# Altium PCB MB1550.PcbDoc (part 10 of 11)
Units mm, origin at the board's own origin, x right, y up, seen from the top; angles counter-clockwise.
Board outline 154.81 x 170.69 mm, 6 copper layers (Top Layer, Signal Layer 1, Signal Layer 2, Signal Layer 3, Signal Layer 4, Bottom Layer), stack 1.49 mm thick; 810 components, 633 nets, 2973 pads, 2150 vias.
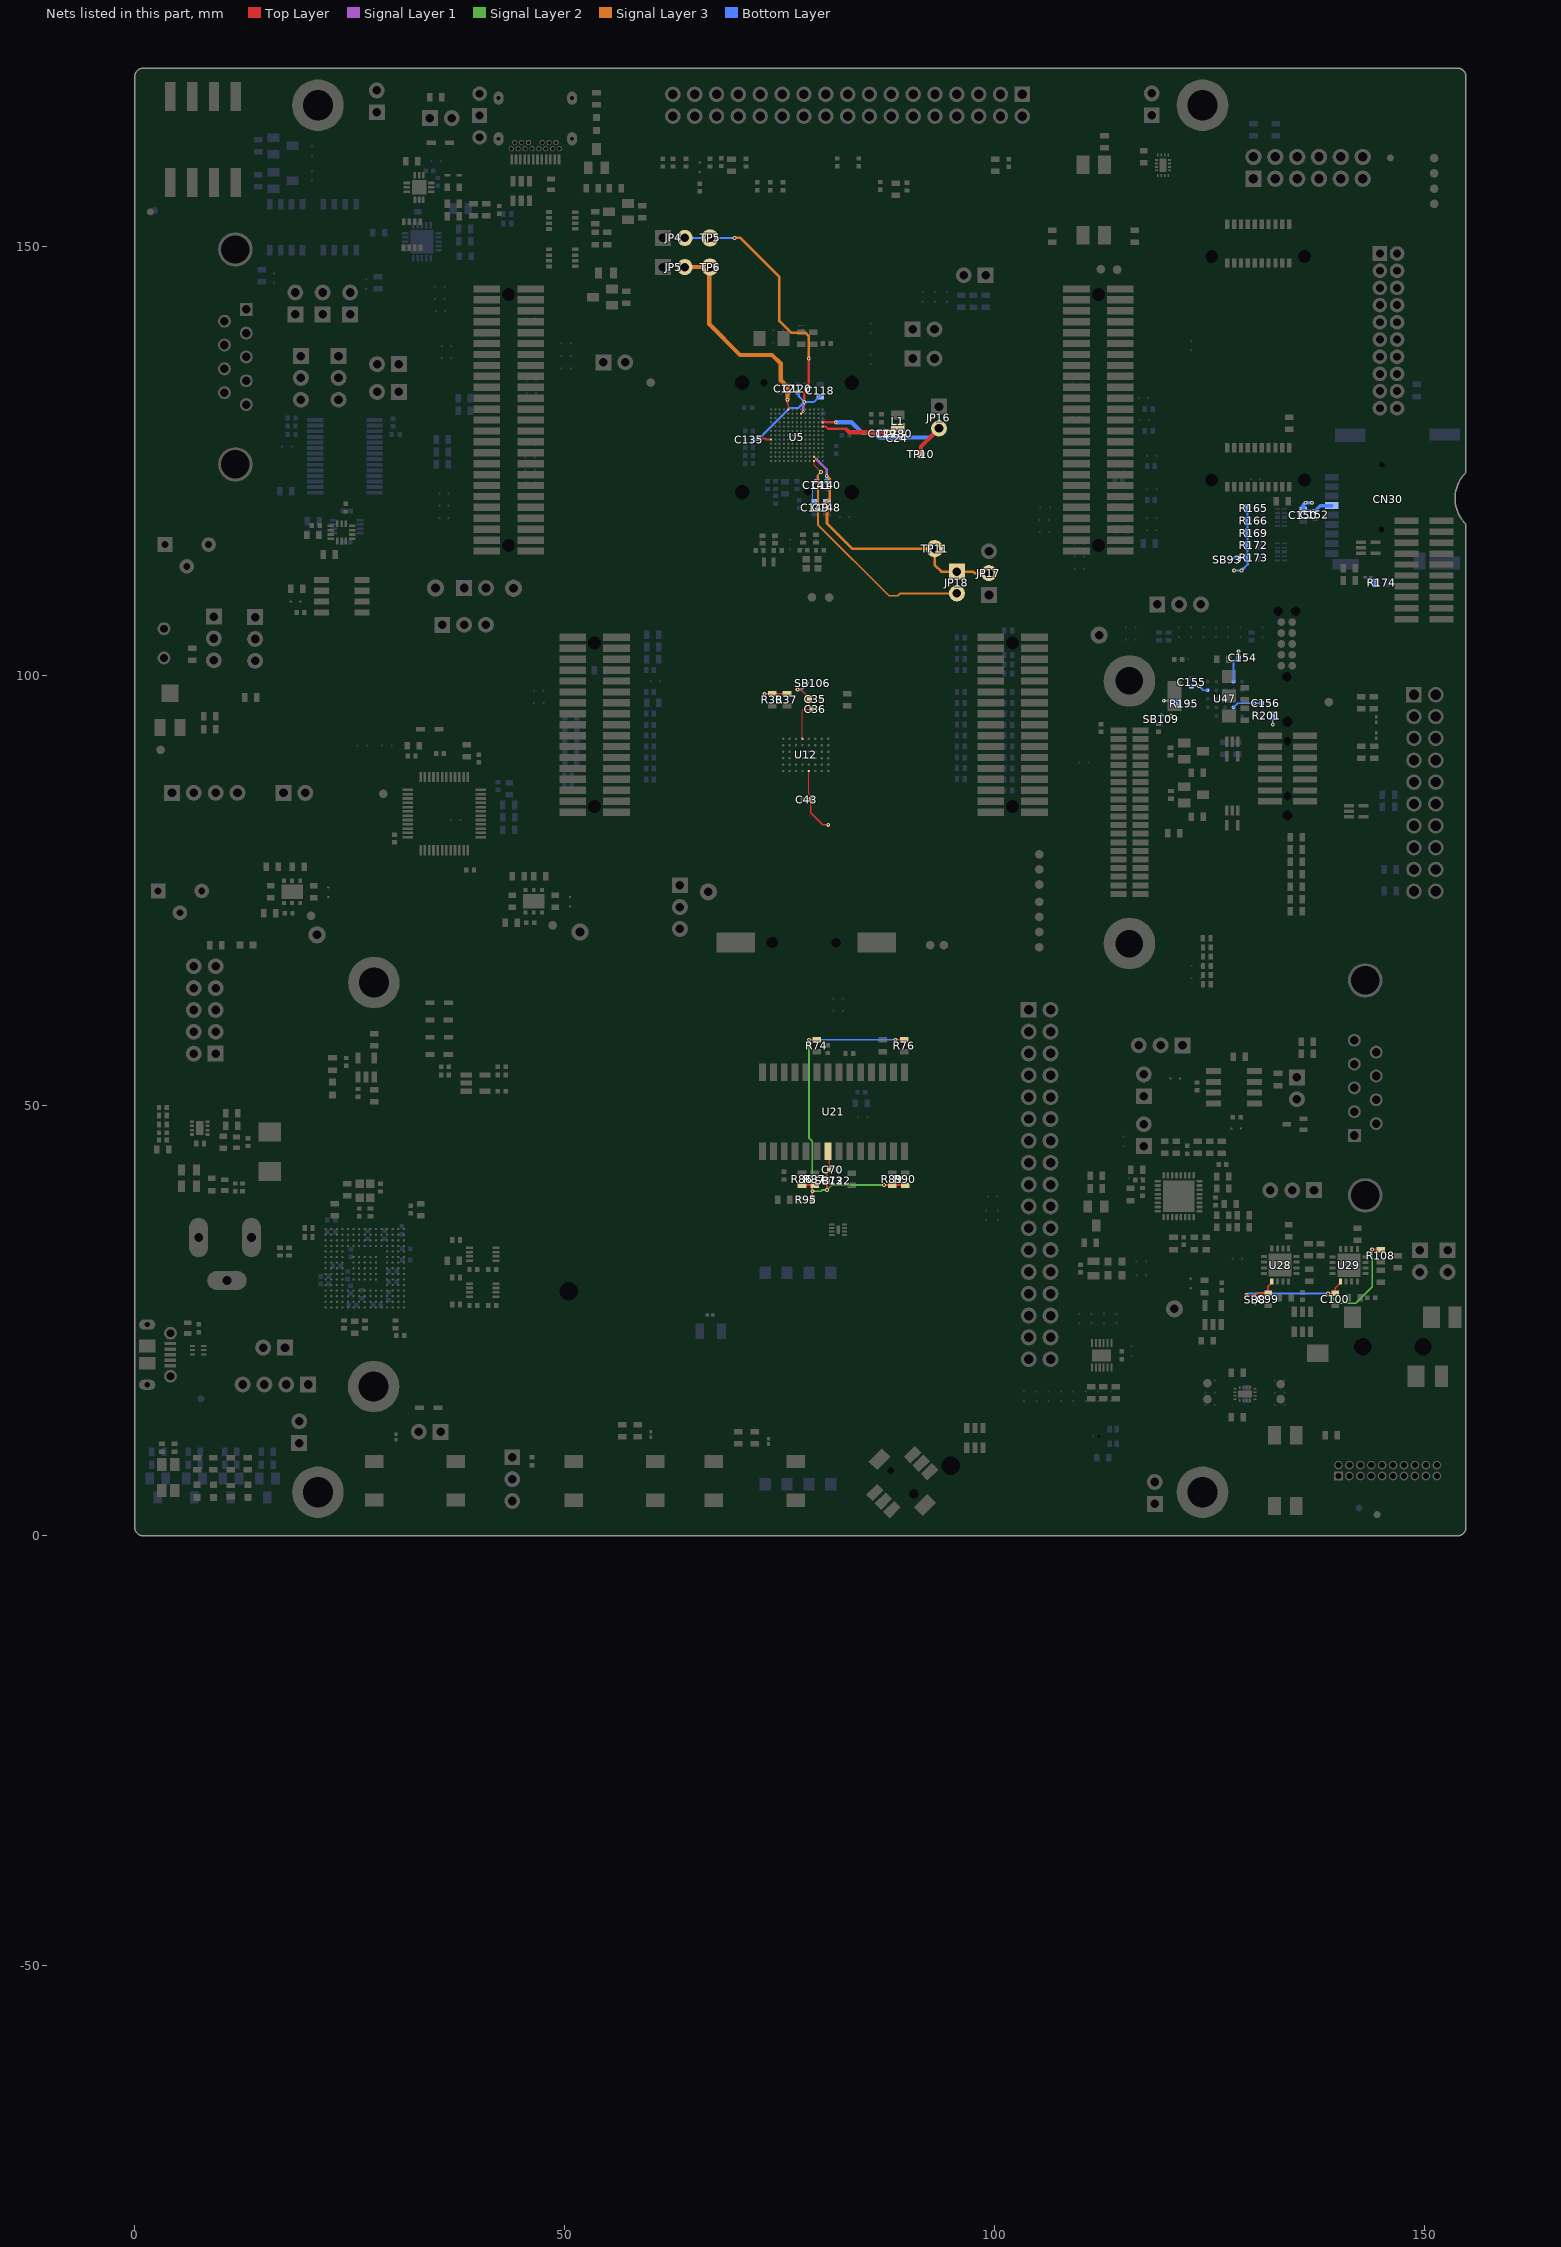
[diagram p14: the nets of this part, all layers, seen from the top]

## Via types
v1: diameter 0.45, hole 0.2, Top Layer to Bottom Layer, tented both sides, 1777 vias
v2: diameter 0.25, hole 0.1, Top Layer to Signal Layer 1, tented top, 344 vias
v3: diameter 0.25, hole 0.1, Signal Layer 1 to Signal Layer 2, 29 vias

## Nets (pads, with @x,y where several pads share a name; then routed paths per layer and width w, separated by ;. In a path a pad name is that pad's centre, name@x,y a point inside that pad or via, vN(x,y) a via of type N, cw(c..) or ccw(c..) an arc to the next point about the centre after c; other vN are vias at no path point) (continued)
VDD_OCTOSPI_2_FLASH: C154.2 C155.2 C156.2 R195.2 R201.1 SB109.2 U47.B4 U47.D1 U47.E4 | length 13.5
  Bottom Layer w0.2: SB109.2@119.384,95.521 119.529,95.375 v1(120.5,95.375) ; v1(119.675,97.125) 121.225,97.125 121.334,97.016 R195.2@121.334,96.771 ; C155.2@122.9,98.825 v1(123.775,98.825) 124.254,98.346 U47.D1@124.784,98.346 ; U47.B4@127.784,96.346 128.262,96.824 v1(130.225,96.825) C156.2@131.05,96.825 ; U47.E4@127.784,99.346 127.784,101.534 C154.2@128.375,102.125 v1(128.375,102.875) ; v1(132.334,94.359) R201.1@132.334,95.371
VDD_SC: C70.1 C73.2 R74.2 R76.2 R86.2 R87.2 R89.2 R90.2 R95.2 SB122.2 U21.21 | length 50.4
  Top Layer w0.2: R86.2@77.6,40.8 R87.2@78.75,40.8 ; v1(78.4,57.7) R74.2@79.3,57.7 ; R95.2@78.8,39.1 78.8,40.7 R87.2@78.725,40.775 ; v1(80.5,40.225) C73.2@80.5,41.3 80.5,42.3 80.75,42.55 C70.1@80.75,42.6 80.75,44.616 U21.21@80.615,44.751 ; v1(87.141,40.807) 87.148,40.8 R89.2@88.1,40.8 R90.2@89.6,40.8 ; v1(88.45,57.7) R76.2@89.5,57.7 ; R87.2@78.725,40.775 R87.2@78.75,40.8 ; R87.2@78.725,40.775 79.075,40.775 R87.2@79.1,40.8 R87.2@78.75,40.8
  Signal Layer 2 w0.2: v1(78.4,57.7) 78.4,46.302 78.8,45.902 v1(78.8,40.075) 79.766,40.075 79.916,40.225 v1(80.5,40.225) 81.083,40.807 v1(87.141,40.807)
  Bottom Layer w0.2: v1(78.4,57.7) v1(88.45,57.7) ; v1(80.5,40.225) 80.5,41.1 SB122.2@80.7,41.3
VDD_SDCARD: C150.1 C152.2 CN30.4 R165.2 R166.2 R169.2 R172.2 R173.2 R174.2 SB93.2 | length 16.4
  Bottom Layer w0.25: SB93.2@127.575,113.525 127.8,113.75 R173.2@129.425,113.75 129.425,112.988 v1(128.699,112.263) 128.687,112.275 v1(127.85,112.275) ; R173.2@129.425,113.75 R172.2@129.425,115.175 R169.2@129.425,116.625 R166.2@129.425,118.05 R165.2@129.425,119.5 ; v1(143.525,110.85) R174.2@144.325,110.85
  Bottom Layer w0.4: v1(136.9,120.15) v1(136.15,120.15) 135.9,119.9 C150.1@135.9,119.4 136.125,119.175 C152.2@137.25,119.175 137.887,119.812 CN30.4@139.198,119.812
VDD_SRAM: C35.2 C36.2 C43.2 R36.1 R37.2 SB106.2 U12.D6 U12.E1 | length 19.2
  Top Layer w0.1: U12.D6@77.65,92.696 77.65,95.975 77.825,96.15 C36.2@78.7,96.15 78.45,96.4 78.45,96.625 ; U12.E1@78.4,88.946 78.4,86.3 78.6,86.1 C43.2@78.6,85.625 78.6,84.85
  Top Layer w0.2: v1(73.25,97.925) R36.1@74.15,97.925 R37.2@75.85,97.925 ; v1(77.095,98.431) 77.433,98.431 78.45,97.414 C35.2@78.45,97.3 78.45,96.625 ; 78.6,84.85 78.6,84.099 80.012,82.687 v1(80.651,82.687)
  Bottom Layer w0.2: v1@77.095,98.436 77.586,98.436 SB106.2@78.3,99.15
VDD_STPMS2: C99.2 C100.2 R108.2 SB8.2 U28.1 U29.1 | length 27.9
  Top Layer w0.2: v1(129.3,28) SB8.2@130.3,28 130.5,28.2 C99.2@131.8,28.2 131.8,29.025 132.225,29.45 U28.1@132.225,29.6 ; v1(138.775,28.2) C100.2@139.6,28.2 139.6,28.825 140.225,29.45 U29.1@140.225,29.58 ; v1(143.9,33.3) R108.2@144.9,33.3
  Signal Layer 2 w0.2: v1(138.775,28.2) 139.915,27.06 141.972,27.06 143.9,28.987 v1(143.9,33.3)
  Bottom Layer w0.2: v1(129.3,28) 129.5,28.2 v1(138.775,28.2)
VDD_USB: C121.2 JP5.2 TP6.1 U5.E13 | length 26.4
  Top Layer w0.2: v1(75.9,132.125) 75.9,131.73 76,131.629 U5.E13@76,131
  Signal Layer 3 w0.5: JP5.2@63.97,147.55 TP6.1@66.9,147.55 66.805,147.455 66.805,140.919 70.396,137.328 74.119,137.328 75.118,136.329 75.118,134.401 75.9,133.619 v1(75.9,132.125)
  Bottom Layer w0.1: v1(75.9,132.125) 75.9,132.9 C121.2@75.975,132.975
VDDA: C140.2 C148.1 JP17.2 JP18.1 TP11.1 U5.L2 | length 32.2
  Top Layer w0.25: U5.L2@79,125.5 v2(79.25,125.25)
  Signal Layer 1 w0.3: v2(79.25,125.25) 80.475,124.025 v1(80.475,123.25)
  Signal Layer 3 w0.3: v1(80.475,123.25) 80.818,122.907 80.818,120.628 80.5,120.31 v1(80.5,119.675) 80.5,117.732 83.432,114.8 TP11.1@93.025,114.8 93.025,112.922 93.807,112.14 JP18.1@95.609,112.14 97.491,112.14 97.671,111.96 JP17.2@99.34,111.96
  Bottom Layer w0.3: C140.2@80.475,122.65 v1(80.475,123.25) ; v1(80.5,119.675) C148.1@80.5,120.275
VDDIO: C118.2 C120.2 C135.2 JP4.2 TP5.1 U5.A6 U5.H12 | length 44.3
  Top Layer w0.25: v1(72.6,127.6) 73.324,127.6 73.424,127.5 U5.A6@74,127.5 ; U5.H12@77.5,130.5 v2(77.75,130.75) ; v1(77.865,131.872) 77.865,132.945 78.375,133.455 v1(78.375,136.925)
  Signal Layer 1 w0.25: v2(77.75,130.75) 77.75,131.472 77.865,131.586 v1(77.865,131.872)
  Signal Layer 3 w0.3: v1(69.75,150.945) 70.43,150.945 71.375,150 74.975,146.4 74.975,141.275 76.325,139.925 78,139.925 78.375,139.55 v1(78.375,136.925)
  Bottom Layer w0.25: JP4.2@63.97,150.945 TP5.1@66.9,150.945 v1(69.75,150.945) ; C135.2@71.9,127.45 72.45,127.45 v1(72.6,127.6) 76.164,131.164 77.157,131.164 v1(77.865,131.872) ; C120.2@77.1,132.975 77.212,132.864 77.212,132.525 v1(77.865,131.872) ; C118.2@79.725,132.475 79.609,132.475 79.006,131.872 v1(77.865,131.872)
VDDSMPS_CIN: C128.2 C129.2 C130.2 JP16.2 TP10.1 U5.N10 | length 18.5
  Top Layer w0.25: U5.N10@80,129.5 v1(81.525,129.5)
  Top Layer w0.5: TP10.1@91.425,125.8 91.425,126.685 JP16.2@93.525,128.785
  Bottom Layer w0.5: v1(81.525,129.5) 83.365,129.5 84.559,128.306 85.97,128.306 86.538,127.737 C129.2@87.013,127.737 C128.2@87.913,127.737 C130.2@88.763,127.737 92.478,127.737 JP16.2@93.525,128.785
VLX: C24.2 L1.2 U5.N9 | length 10.7
  Top Layer w0.102: L1.2@88.635,128.759 L1.2@88.725,128.85
  Top Layer w0.2: 82.705,128.745 82.783,128.667
  Top Layer w0.25: U5.N9@80,129 80.364,129 80.618,128.745 82.705,128.745
  Top Layer w0.5: 82.783,128.667 83.117,128.333 87.794,128.333 88.073,128.612 88.488,128.612 L1.2@88.725,128.85 89.15,128.425 C24.2@89.15,127.625
VREFP: C141.2 C149.1 JP18.2 U5.L1 | length 31.5
  Top Layer w0.08: U5.L1@79,125 79,124.525 v1(79.8,123.725)
  Signal Layer 3 w0.2: v1(79.8,123.725) 79.446,123.371 79.446,117.599 87.72,109.325 88.75,109.325 89.025,109.6 JP18.2@95.609,109.6
  Bottom Layer w0.1: C149.1@79.125,120.275 78.875,120.525 78.875,122.175 C141.2@79.35,122.65 79.35,123.275 v1(79.8,123.725)
pads on no net: B1.NPTH1 B1.NPTH2 CN1.A2 CN1.A3 CN1.A8 CN1.A10 CN1.A11 CN1.B2 CN1.B3 CN1.B8 CN1.B10 CN1.B11 CN3.9 CN3.10 CN4.1 CN4.3 CN4.7 CN5.5 CN5.6 CN5.7 CN5.8 CN5.9 CN5.10 CN5.11 CN5.12 CN5.NPTH1 CN5.NPTH2 CN6.1 CN6.4 CN6.9 CN9.NPTH1 CN9.NPTH2 CN10.NPTH1 CN10.NPTH2 CN11.NPTH1 CN11.NPTH2 CN12.7 CN13.7 CN13.11 CN13.12 CN13.13 CN14.3 CN14.5 CN14.29 CN14.30 CN14.NPTH1 CN14.NPTH2 CN15.29 CN15.NPTH1 CN15.NPTH2 CN16.5 CN16.6 CN16.9 CN16.10 CN18.0 CN18.1 CN18.2 CN18.9 CN21.NPTH1 CN21.NPTH2 CN22.1 CN22.4 CN22.8 CN23.29 CN26.4 CN27.5 CN27.7 CN27.MT1 CN27.MT2 CN29.8 CN29.9 CN29.10 CN29.11 CN29.13 CN29.14 CN29.15 CN29.16 CN29.17 CN29.18 CN30.NPTH1 CN30.NPTH2 CN31.C6 CN31.NPTH1 CN31.NPTH2 Mire1.1 Mire2.1 Mire3.1 Mire4.1 Mire5.1 Mire6.1 U1.17 U3.5 U5.0 U6.9 U6.10 U6.11 U12.E3 U15.3 U15.4 U15.5 U15.6 U15.25 U15.38 U21.10 U21.25 U25.19 U25.20 U25.23 U25.24 U26.A1 U26.A2 U26.A3 U26.A4 U26.A5 U26.A6 U26.A8 U26.A9 U26.A10 U26.A11 U26.A12 U26.A13 U26.B1 U26.B2 U26.B3 U26.B4 U26.B5 U26.B6 U26.B7 U26.B8 U26.B9 U26.B10 U26.B11 U26.B12 U26.B13 U26.B14 U26.B15 U26.C2 U26.C3 U26.C4 U26.C11 U26.C12 U26.C13 U26.C14 U26.C15 U26.D1 U26.D2 U26.D3 U26.D4 U26.D10 U26.D11 U26.D13 U26.D14 U26.E1 U26.E2 U26.E3 U26.E4 U26.E12 U26.E13 U26.E14 U26.E15 U26.F1 U26.F4 U26.F14 U26.G4 U26.G14 U26.G15 U26.H1 U26.H2 U26.H3 U26.H4 U26.H14 U26.H15 U26.J2 U26.J3 U26.J4 U26.K1 U26.K2 U26.K3 U26.K12 U26.K14 U26.K15 U26.L1 U26.L3 U26.L12 U26.L13 U26.L14 U26.L15 U26.M2 U26.M3 U26.M4 U26.M5 U26.M6 U26.M7 U26.M12 U26.M13 U26.M14 U26.M15 U26.N2 U26.N4 U26.N5 U26.N6 U26.N7 U26.N11 U26.N13 U26.N14 U26.N15 U26.P2 U26.P4 U26.P5 U26.P6 U26.P7 U26.P8 U26.P9 U26.P10 U26.P11 U26.P12 U26.P13 U26.P14 U26.P15 U26.R2 U26.R3 U26.R6 U26.R7 U26.R8 U26.R9 U26.R10 U26.R11 U26.R12 U26.R13 U27.2 U28.16 U29.16 U36.4 U37.7 U37.12 U37.17 U43.8 U43.11 U43.12 U43.15 U43.18 U43.19 U43.21 U46.4 U46.5 U46.6 U46.7 U47.A2 U47.B1 U47.B5 U48.6
copper on no net:
  other v2: 47.8,78.1 19.7,79.2

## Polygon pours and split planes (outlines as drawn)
GND on Top Layer "NO_TH" (solid, pour order 216): -0.141,172.917 154.285,172.917 157.49,169.712 157.49,0.45 154.522,-2.518 0.215,-2.518 -3.055,0.753 -3.055,170.887 -1.026,172.916
5V_EXT on Top Layer "NO_TH" (solid, pour order 214): 7.649,45.232 7.649,46.04 8.094,46.486 8.094,46.829 8.211,46.946 12.585,46.946 14.228,48.59 17.454,48.59 17.925,48.119 17.925,45.824 17.548,45.447 13.993,45.447 13.652,45.788 9.326,45.788 8.63,45.092 7.757,45.092 7.651,45.198
5V_UNPROTECT on Top Layer "NO_TH" (solid, pour order 215): 6.999,46.588 7.523,46.064 7.523,45.182 7.433,45.091 6.837,45.091 6.493,45.436 6.493,46.073 6.107,46.466 4.783,46.466 4.652,46.335 4.652,44.83 6.182,43.299 6.182,41.786 6.183,41.754 6.049,41.62 4.577,41.62 3.28,42.917 3.28,47.135 3.569,47.424 6.92,47.424 6.999,47.345
GND_EXT_UNFILT on Top Layer "NO_TH" (solid, pour order 213): 13.927,28.587 13.927,30.169 11.224,32.872 11.224,36.754 13.32,38.85 13.32,40.187 12.969,40.538 8.55,40.538 7.641,41.447 6.578,41.447 6.335,41.203 6.335,39.03 5.312,38.007 5.312,30.463 7.709,28.065 13.469,28.065 13.928,28.525 13.928,28.569
5V_EXT_UNFILT on Top Layer "NO_TH" (solid, pour order 176): 15.588,33.276 15.588,39.761 12.879,42.471 9.609,42.471 8.541,43.538 6.625,43.538 6.338,43.251 6.338,41.842 6.625,41.554 7.707,41.554 8.678,40.583 12.988,40.583 13.358,40.213 13.358,38.708 11.387,36.738 11.387,32.947 12.851,31.483 14.411,31.483 14.411,31.511 15.602,32.701
UCPD_SOURCE on Top Layer "NO_TH" (solid, pour order 158): 45.368,150.493 44.125,149.25 44.125,147.6 44.95,146.775 47,146.787 49.986,146.787 50.39,147.192 50.39,150.285 50.292,150.391 50.19,150.493
3V3 on Top Layer "NO_TH" (solid, pour order 175): 52.782,68.783 51.119,68.783 49.874,70.027 49.874,73.174 50.003,73.303 51.776,73.303 53.12,71.959 53.12,68.9 53.002,68.782
VBUSc on Top Layer "NO_TH" (solid, pour order 151): 47.65,150.575 49.456,150.575 50.2,151.319 50.2,154.504 49.87,154.834 48.404,154.834 47.49,153.921 47.49,150.677 47.594,150.573
NetC115_1 on Top Layer "NO_TH" (solid, pour order 174): 17.325,156.75 19.775,156.75 22.25,154.275 27.9,154.275 29.55,152.625 29.55,152.175 29.275,151.9 22.95,151.9 19.725,155.125 17.425,155.125 17,155.55 17,156.425
NetC19_2 on Top Layer "NO_TH" (solid, pour order 140): 52.475,153.1 52.475,151.285 52.81,150.95 55.4,150.95 55.825,150.525 55.825,149.675 55.425,149.275 53.375,149.275 52.65,148.55 52.65,147.6 52.162,147.112 50.74,147.112 50.625,147.227 50.625,149.1 50.75,149.225 51.675,149.225 52,149.55 52,150.075 51.825,150.075 50.65,151.25 50.65,153.55 50.75,153.65 51.925,153.65
5V on Top Layer "NO_TH" (solid, pour order 141): 14.575,76.95 17.5,76.95 17.825,76.625 17.825,75.725 17.1,75 14.625,75 14.15,75.475 14.15,76.525
NetC47_2 on Top Layer "NO_TH" (solid, pour order 142): 21.95,78.5 23.35,77.1 23.35,75.65 22.8,75.1 19.5,75.1 18.825,75.775 18.825,77.1 19,77.275 19,78.2 19.3,78.5
NetC49_2 on Top Layer "NO_TH" (solid, pour order 143): 50.1,77.325 51.5,75.925 51.5,74.475 50.95,73.925 47.65,73.925 46.975,74.6 46.975,75.925 47.15,76.1 47.15,77.025 47.45,77.325
5V on Top Layer "NO_TH" (solid, pour order 144): 42.725,75.775 45.65,75.775 45.975,75.45 45.975,74.55 45.25,73.825 42.775,73.825 42.3,74.3 42.3,75.35
5V_USB_CHGR on Top Layer "NO_TH" (solid, pour order 145): 24.225,56.9 26.125,56.9 26.675,56.35 26.675,54.85 26.475,54.65 25.625,54.65 25.15,55.125 21.675,55.125 21.4,55.4 21.4,56.525 21.775,56.9 23.725,56.9
NetC55_1 on Top Layer "NO_TH" (solid, pour order 147): 39.6,53.925 37.575,55.95 37.575,62.625 37.3,62.9 35.975,62.9 35.475,62.4 35.475,55.8 36.075,55.2 36.075,51.675 36.95,50.8 39.25,50.8 39.6,51.15
3V3 on Top Layer "NO_TH" (solid, pour order 148): 126.675,25.75 127.3,25.125 127.3,23.775 127,23.475 125.025,23.475 124.8,23.25 124.8,22.175 124.3,21.675 123.2,21.675 122.825,22.05 122.825,25.075 123.5,25.75
3V3_STLK on Top Layer "NO_TH" (solid, pour order 156): 40.14,52.837 42.416,52.838 42.734,53.155 42.734,54.813 43.192,55.271 45.021,55.271 45.485,55.735 45.485,56.339 45.13,56.694 41.04,56.694 39.924,55.577 39.924,53.058
NetC34_2 on Top Layer "NO_TH" (solid, pour order 168): 129.927,98.966 129.927,98.321 129.559,97.953 128.572,97.953 128.401,97.782 128.401,96.795 128.164,96.558 123.309,96.558 122.177,95.426 119.717,95.426 119.519,95.624 119.519,102.163 119.861,102.506 121.177,102.506 121.361,102.321 121.361,101.374 123.809,98.926 128.046,98.926 128.367,99.247 129.644,99.247
UCPD_SNK01 on Top Layer "NO_TH" (solid, pour order 173): 32.825,155.8 32.825,154.15 33.738,153.237 33.738,152.261 33.576,152.1 31.725,152.1 31.6,152.225 31.6,154.05 30.95,154.7 28.35,154.7 28.075,154.975 28.075,155.5 28.425,155.85 32.5,155.85 32.775,155.85
GND on Signal Layer 1 "NO_TH" (solid, pour order 177): -0.01,173.806 154.415,173.806 157.62,170.601 157.62,1.339 154.652,-1.629 0.346,-1.629 -2.925,1.642 -2.925,171.776 -0.896,173.805
TS_SHIELD on Signal Layer 1 "NO_TH" (solid, pour order 149): 84.5,141 84.5,155 70.5,155 70.5,141 76.5,141 76.725,140.775 76.725,138.425 77.5,137.65 77.5,135.876 77.25,135.626 77.25,131.442 77.759,130.933 77.858,130.933 78.019,131.094 78.019,135.594 78.25,135.825 78.25,137.1 79.575,138.425 79.575,140.625 79.95,141
VDD on Signal Layer 3 "NO_TH" (solid, pour order 196): 0.069,174.286 159.456,174.286 159.456,-7.077 -6.751,-7.077 -6.751,174.286 0.026,174.286
UCPD_SOURCE on Signal Layer 3 "NO_TH" (solid, pour order 194): 45.8,147.6 45.8,148.55 45.225,149.125 43.675,149.125 40.7,146.15 33.079,146.15 28.954,150.275 28.55,150.275 28.25,149.975 28.25,145.34 29.665,143.925 40.475,143.925 43.95,147.4 45.6,147.4
VDD_MCU on Signal Layer 3 "NO_TH" (solid, pour order 160): 39.646,110.091 40.634,109.103 51.414,109.103 52.775,107.703 100.363,107.703 101.076,108.416 101.076,126.321 73.935,153.462 60.734,153.462 60.598,153.455 59.875,152.731 59.875,124.269 57.928,122.322 33.347,122.322 27.602,116.577 27.602,99.959 32.221,95.34 32.221,84.249 34.369,82.101 36.677,82.101 37.641,83.064 37.641,96.41 32.221,101.735 32.221,113.668 34.575,116.022 39.171,116.022 39.646,115.547
NetQ12_1 on Signal Layer 3 "NO_TH" (solid, pour order 182): 25.525,155.35 26.55,156.375 29.35,156.375 32.325,153.4 34.25,153.4 34.525,153.675 34.525,154.7 31.625,157.6 22.875,157.6 21.925,156.65 21.925,155.6 22.175,155.35
VDD_SDCARD on Signal Layer 3 "NO_TH" (solid, pour order 161): 137.167,120.525 135.875,120.525 132.95,117.6 129.3,117.605 129.28,117.605 127.525,115.85 127.525,110.95 129.05,109.425 143.449,109.425 144.23,110.207 144.23,113.462
VDD_OCTOSPI_2_FLASH on Signal Layer 3 "NO_TH" (solid, pour order 139): 119.275,95.875 120.575,94.575 131.275,94.575 131.95,93.9 132.525,93.9 132.875,94.25 132.875,94.992 129.875,97.992 129.875,103.075 129.425,103.525 126.875,103.525 121.175,97.825 119.809,97.825 119.275,97.291
VDD_SRAM on Signal Layer 3 "NO_TH" (solid, pour order 155): 72.669,99.465 77.56,99.465 81.353,95.672 81.353,82.53 80.82,81.998 80.055,81.998 79.523,82.53 79.523,94.674 77.393,96.803 73.134,96.803 72.17,97.768 72.17,98.966
VDD_ADJ on Signal Layer 3 "NO_TH" (solid, pour order 166): 43.078,107.048 40.527,107.048 39.886,106.407 39.886,94.954 45.975,88.865 45.975,77.909 40.961,72.896 26.895,72.896 24.841,74.949 23.247,74.949 22.834,74.536 22.834,73.414 26.167,70.081 41.369,70.081 48.462,77.174 48.462,101.663 43.448,106.677
2V8 on Signal Layer 3 "NO_TH" (solid, pour order 150): 119.506,105.776 114.601,105.776 110.979,102.154 111.004,94.675 111.004,94.142 110.977,94.115 111.276,93.815 115.852,93.815 117.977,91.69 117.977,87.523 118.549,86.951 119.966,86.951 120.865,87.849 120.865,95.231 124.133,98.5 124.133,103.267 121.627,105.773 119.993,105.773
VBUSc on Signal Layer 3 "NO_TH" (solid, pour order 152): 45.156,153.25 41.039,153.25 40.74,152.951 40.74,150.455 39.534,149.25 36.65,149.25 36.4,149.5 36.4,152.5 36.696,152.804 36.758,152.867 36.758,158.345 37.953,159.541 40.74,159.541 44.074,162.875 49.059,162.875 50.327,161.607 50.327,160.604 56.75,154.18 56.75,145.875 56.623,145.748 52.659,145.748
VDD_MFX on Signal Layer 3 "NO_TH" (solid, pour order 153): 30.287,91.399 30.955,90.731 30.955,83.353 32.976,81.332 36.736,81.332 39.085,83.682 39.085,90.778 39.696,91.399 40.348,91.399 45,86.746 45,80.993 38.899,74.892 34.939,74.892 21.655,88.176 6.698,88.176 5.912,87.39 5.912,85.11 5.519,84.717 2.886,84.717 2.375,85.228 2.375,88.53 5.244,91.399
VDD_OCTOSPI_1_MOD on Signal Layer 3 "NO_TH" (solid, pour order 154): 122.547,138.522 123.792,139.767 124.592,139.767 125.293,140.468 125.293,143.759 133.104,151.57 141.095,151.57 141.676,150.983 141.676,130.407 133.784,122.514 133.019,122.514 122.547,132.987
3V3_STLK on Signal Layer 3 "NO_TH" (solid, pour order 157): 43.321,26.074 42.575,26.82 42.575,29.982 40.394,32.163 36.154,32.163 35.392,31.401 35.392,26.822 34.644,26.074 24.779,26.074 23.149,24.444 23.149,16.438 22.04,15.329 8.475,15.329 5.887,12.741 5.887,3.885 5.051,3.068 4.882,2.899 4.324,2.899 3.691,3.532 3.691,13.136 10.589,20.034 19.602,20.034 20.8,21.232 20.8,38.73 24.06,41.99 40.504,41.99 43.332,44.819 43.332,56.468 43.907,57.044 45.058,57.044 45.633,56.468 45.633,26.937 44.77,26.074
5V_USB_CHGR on Signal Layer 3 "NO_TH" (solid, pour order 165): 34.139,62.685 34.139,61.874 29.388,57.124 29.388,50.572 28.87,50.054 24.863,50.054 10.552,64.365 7.187,64.365 3.567,60.745 3.567,30.248 8.673,25.142 8.673,23.703 8.116,23.146 7.002,23.146 0.735,29.412 0.735,65.34 3.938,68.543 12.665,68.543 20.092,61.116 29.329,61.116 31.204,62.992 33.839,62.992
UCPD_SOURCE on Signal Layer 3 "NO_TH" (solid, pour order 188): 26.225,144.325 26.225,151.3 26.873,151.948 27.463,151.948 27.875,152.36 27.875,153.275 27.6,153.55 26.675,153.55 23.68,150.555 23.68,143.97 24.125,143.525 25.425,143.525
UCPD_SNK01 on Signal Layer 3 "NO_TH" (solid, pour order 192): 23.15,144.05 23.15,150.65 26.625,154.125 28.55,154.125 29.425,155 29.425,155.725 29,156.15 26.725,156.15 20.275,149.7 20.275,144.125 20.825,143.575 22.655,143.575 22.955,143.875
3V3 on Signal Layer 4 "NO_TH" (solid, pour order 212): 20.356,174.745 164.396,174.745 164.396,-7.258 -10.629,-7.258 -10.629,174.745
5V_UCPD on Signal Layer 4 "NO_TH" (solid, pour order 208): 11.307,126.691 17.353,132.738 17.353,138.851 19.266,140.764 26.015,140.764 26.617,141.366 26.617,142.877 26.183,143.311 7.8,143.311 7.8,133.432 7.8,58.2 8.575,57.425 33.6,57.425 33.9,57.725 33.9,58.525 33.6,58.825 20.4,58.825 17.925,61.3 16.875,62.35 16.875,85.275 11.307,90.843 11.307,98.55
5V on Signal Layer 4 "NO_TH" (solid, pour order 167): 28.55,162.725 26.45,162.725 24.975,161.25 13.725,161.25 13.315,160.81 7.476,154.971 7.476,71.249 8.375,70.35 8.375,55.125 3.05,49.8 3.05,28.35 5.875,25.525 5.875,6.55 9.775,2.65 86.15,2.65 86.875,1.925 86.875,-0.4 86.025,-1.25 -0.45,-1.25 -5.3,3.6 -5.227,35.3 -5.227,168.689 -4.491,168.689 3.31,176.49 152.269,176.49 156.685,172.074 156.685,129.55 156.725,36.325 155.7,35.3 153.2,35.3 152.675,35.825 152.675,104.95 149.575,108.05 149.575,121.6 142.8,128.375 142.8,150.5 145.55,153.25 145.55,160.4 144.15,161.8 117.549,161.8 117.112,162.237 114.77,164.579 109.508,164.579 107.654,162.725
UCPD_SNK03 on Signal Layer 4 "NO_TH" (solid, pour order 206): 27.575,150.6 27.381,150.794 25.331,150.794 25.281,150.744 23.175,148.625 18.85,148.625 16.95,146.725 16.95,143.95 17.525,143.375 19.65,143.375 20.25,143.975 20.25,145.175 21.3,146.225 24.35,146.225 27.575,149.45
NetQ13_1 on Signal Layer 4 "NO_TH" (solid, pour order 204): 14.65,155.175 16.75,155.175 19.475,157.9 26.125,157.9 30,154.025 30,153.075 29.825,152.9 29.275,152.9 25.175,157 21.025,157 18.475,154.45 14.55,154.45 14.4,154.6 14.4,154.925 14.65,155.175 14.875,155.175
5V_DC on Signal Layer 4 "NO_TH" (solid, pour order 210): 35.284,116.275 36.151,115.408 36.151,114.351 35.9,114.1 16.95,114.1 15.4,112.625 15.4,93.75 21.625,87.525 21.625,84.85 18.975,82.2 18.975,63.3 21.35,60.925 33.325,60.925 34.175,60.075 34.175,59.35 33.95,59.125 20.533,59.125 17.181,62.477 17.181,85.402 11.612,90.97 11.612,115.99 11.898,116.275
GND on Signal Layer 2 "NO_TH" (solid, pour order 179): -0.622,173.798 153.803,173.798 157.008,170.593 157.008,1.33 154.04,-1.637 -0.266,-1.637 -3.537,1.634 -3.537,171.767 -1.508,173.797
5V_EXT on Signal Layer 2 "NO_TH" (solid, pour order 163): 11.969,56.867 18.391,50.445 18.391,45.71 17.58,44.898 11.535,44.898 3.025,53.418 3.025,57.729 5.325,60.029 10.748,60.029 11.969,58.808
GND on Bottom Layer "NO_TH" (solid, pour order 202): -0.253,172.689 154.172,172.689 157.377,169.484 157.377,0.222 154.41,-2.746 0.103,-2.746 -3.168,0.525 -3.168,170.659 -1.138,172.688
VDD_SDCARD on Bottom Layer "NO_TH" (solid, pour order 198): 129.05,111.925 130,112.875 130,114.3 129.85,114.45 127.675,114.45 127.375,114.15 127.375,112.075 127.525,111.925
2V8 on Bottom Layer "NO_TH" (solid, pour order 172): 122.227,102.715 122.227,101.304 122.442,101.089 123.561,101.089 124.063,101.591 124.063,102.727 123.852,102.938 122.361,102.938 122.227,102.803 122.227,102.793
NetC34_2 on Bottom Layer "NO_TH" (solid, pour order 171): 119.802,100.988 119.802,102.188 120.177,102.563 121.354,102.563 121.427,102.489 121.427,101.267 120.962,100.801 119.989,100.801
VDD_SDCARD on Bottom Layer "NO_TH" (solid, pour order 190): 140.025,120.45 135.95,120.45 135.275,119.775 135.275,118.875 135.45,118.7 137.525,118.7 138.075,119.25 140.075,119.25 140.225,119.4 140.225,120.25
NetC114_2 on Bottom Layer "NO_TH" (solid, pour order 169): 17.575,148.75 17.575,153.375 17.7,153.5 20.625,153.5 20.875,153.25 20.875,148.95 21.3,148.525 23.59,148.525 23.8,148.735 23.8,153.325 23.975,153.5 28.15,153.5 29.625,154.975 33.35,154.975 33.675,154.65 35.825,154.65 36.575,155.4 37.7,155.4 38.175,154.925 38.175,153.775 38.3,153.65 39.275,153.65 39.425,153.8 39.425,155.3 38.625,156.1 36.15,156.1 35.323,155.273 34.402,155.273 33.025,156.65 28.3,156.65 25.675,154.025 14.95,154.025 14.5,153.575 14.5,149.025 14.95,148.575 17.4,148.575
UCPD_SNK03 on Bottom Layer "NO_TH" (solid, pour order 170): 27.775,150.225 26.825,151.175 26.825,153.15 26.55,153.425 23.95,153.425 23.875,153.35 23.875,148.894 24.219,148.55 27.35,148.55 27.775,148.975
UCPD_SOURCE on Bottom Layer "NO_TH" (solid, pour order 200): 17.675,153.35 17.775,153.45 20.55,153.45 20.725,153.275 20.725,148.775 21.175,148.325 27.325,148.325 27.95,148.95 27.95,150.175 27.025,151.1 27.025,153.025 27.25,153.25 28.15,153.25 28.5,152.9 28.5,150.9 29.125,150.275 29.125,148.2 28.325,147.4 17.9,147.4 17.675,147.625
VBUSc on Bottom Layer "NO_TH" (solid, pour order 138): 36.6,155.2 37.525,155.2 37.8,154.925 37.8,153.425 38.75,153.425 38.85,153.325 38.85,153.125 38.625,152.9 36.85,152.9 36.375,153.375 36.375,154.975
VDD on Bottom Layer "NO_TH" (solid, pour order 186): 126.5,114.3 125,114.3 124.8,114.1 124.8,113.025 124.93,112.895 126.445,112.895 126.575,113.025 126.575,114.225

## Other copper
Top Layer:
  region net VBUSc: 32.8,151.8 33.705,151.8 34.585,150.92 37.95,150.92 37.95,149.5 37.85,149.4 32.7,149.4 32.675,149.425 32.675,151.612 32.863,151.8
  text "1" at 146.1,2.925 h1.5
  text ".Layer_Name" at 34.834,-69.2 h3
  text ".GTL" at 76.528,-69.2 h3
Signal Layer 1:
  text "2" at 147.35,2.925 h1.5
  text ".Layer_Name" at 34.834,-69.2 h3
  text ".G1" at 76.528,-69.2 h3
Signal Layer 2:
  text "3" at 148.6,2.925 h1.5
  text ".Layer_Name" at 34.834,-69.2 h3
  text ".G2" at 76.528,-69.2 h3
Signal Layer 3:
  text "4" at 149.85,2.925 h1.5
  text ".Layer_Name" at 34.865,-69.183 h3
  text ".G3" at 76.56,-69.183 h3
Signal Layer 4:
  text "5" at 151.1,2.925 h1.5
  text ".Layer_Name" at 34.865,-69.183 h3
  text ".G4" at 76.56,-69.183 h3
Bottom Layer:
  text "6" at 152.35,2.925 h1.5
  text ".GBL" at 65.325,-69.232 h3
  text ".Layer_Name" at 106.639,-69.232 h3
Multi-Layer:
  pour cut-out: 145.975,4.3 145.975,2.55 153.6,2.55 153.6,4.3

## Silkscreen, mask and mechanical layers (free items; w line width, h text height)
Top Overlay:
  lines w0.1: 109.679,89.976 109.679,59.192 110.195,58.676 138.171,58.676 ; 109.685,98.99 109.685,102.209 110.639,103.163 118.71,103.163 119.891,101.983 ; 117.643,150.308 117.643,155.025 143.664,155.025 ; 119.501,117.5 143.664,117.5 ; 125.681,90.4 125.681,84.483 ccw(c129.586,84.483) 129.586,80.578 131.169,80.578 ; 136.735,80.55 137.842,80.55 138.701,79.692 138.701,59.203 138.174,58.676 ; 111.025,10.175 114.625,10.175 114.625,12.925 111.025,12.925 111.025,10.175
  lines w0.127: 68.377,139.772 68.377,148.759 70.099,148.759 70.099,139.772 ; 68.384,139.768 70.107,139.768 ; 86.114,121.649 99.58,121.649 99.58,123.449 86.114,123.449 86.114,121.651 ; 90.172,116.693 95.797,116.693 ; 90.172,116.694 90.172,118.493 95.82,118.493 95.82,116.694 ; 3.371,82.4 13.333,82.4 13.333,84.36 3.371,84.36 3.371,82.4 ; 3.75,153.235 3.75,154.957 9.95,154.957 9.95,153.235 3.75,153.235 ; 14.971,82.4 14.971,84.36 25.5,84.36 25.5,82.4 14.971,82.4 ; 28.136,109.05 32.388,109.05 32.388,111.05 28.136,111.05 28.136,109.05 ; 29.65,0.684 35.85,0.684 35.85,2.384 29.65,2.384 29.65,0.684 ; 33.1,168.547 37.982,168.547 37.982,170.247 33.1,170.247 33.1,168.547 ; 46.75,109.1 46.75,111.2 48.925,111.2 53.675,111.2 55.95,111.2 55.95,109.1 53.875,109.1 49.125,109.1 46.75,109.1 ; 51.8,0.684 51.8,2.384 59.8,2.384 59.8,0.684 51.8,0.684 ; 65.438,76.426 70.4,76.426 70.4,78.126 65.438,78.126 65.438,76.426 ; 68.371,149.702 68.371,156.043 70.071,156.043 70.071,149.702 68.371,149.702 ; 69.202,0.7 69.202,2.4 74.662,2.4 74.662,0.7 69.202,0.7 ; 84.761,159.29 84.761,160.99 88.836,160.99 96.986,160.99 99.252,160.99 99.252,159.29 84.761,159.29 ; 91.018,70.179 92.74,70.179 92.74,77.9 91.018,77.9 91.018,70.179 ; 92.225,106.86 93.925,106.86 93.925,113.3 92.225,113.3 92.225,106.86 ; 93.218,70.179 93.218,77.9 94.94,77.9 94.94,70.179 93.218,70.179 ; 94.24,0.768 103.14,0.768 103.14,2.468 94.24,2.468 94.24,0.768
  text "USB1" at 51.823,169.424 h1.7
  text "BOOT0" at 33.425,168.925 h1.5
  text "PMOD" at 145.05,167.875 h2
  text "1" at 37.975,166.95 h2
  text "GND" at 31.2,164.975 h2 r90
  text "GND" at 116.51,164.316 h2 r90
  text "5V_USB" at 56,161.9 h1.7 r90
  text "0" at 37.8,161.675 h2
  text "MOTOR CONTROL" at 84.928,159.516 h1.8
  text "1" at 105.093,156.875 h2
  text "RS232" at 4.25,153.475 h2
  text "0" at 104.992,152.923 h2
  text "00 : SPI INTERFACE" at 87.483,152.808 h1.5
  text "10 : MikroBus INTERFACE" at 87.579,151.556 h1.5
  text "STMOD+" at 146.7,151.4 h2
  text "11 : UART INTERFACE" at 87.547,150.272 h1.5
  text "VDDIO" at 69.871,149.902 h2 r90
  text "ADC/DAC" at 93.757,148.605 h2
  text "I2C_SCL" at 113.998,148.47 h2
  text "I2C_SDA" at 105.768,148.423 h2
  text "UCPD_SNK01" at 22.595,147.725 h1.6 r90
  text "UCPD_SRC" at 25.759,147.676 h1.6 r90
  text "UCPD_SNK03" at 19.425,147.625 h1.6 r90
  text "MB1242A" at 143,146.375 h2 r90
  text "PA15" at 48.166,144.677 h1.25
  text "PA11" at 36.252,144.58 h1.25
  text "PA9" at 105.147,144.587 h1.25
  text "PA13" at 116.589,144.587 h1.25
  text "PC6" at 48.166,143.377 h1.25
  text "PA10" at 105.147,143.387 h1.25
  text "PA14" at 116.589,143.287 h1.25
  text "PA12" at 36.24,143.269 h1.25
  text "PC7" at 48.166,142.177 h1.25
  text "PI1" at 105.147,142.087 h1.25
  text "PI2" at 116.589,142.087 h1.25
  text "PH2" at 36.24,142.069 h1.25
  text "5V_UCPD" at 26.95,141.25 h2
  text "PI4" at 116.589,140.887 h1.25
  text "PH13" at 48.166,140.877 h1.25
  text "PI3" at 105.147,140.787 h1.25
  text "PH3" at 36.24,140.769 h1.25
  text "VDD_USB" at 69.788,139.908 h2 r90
  text "UCPD_DBCC2" at 94.56,139.775 h1.7
  text "GND" at 48.166,139.577 h1.25
  text "GND" at 116.464,139.537 h1.25
  text "PH15" at 36.2,139.413 h1.25
  text "PI5" at 105.124,139.418 h1.25
  text "UCPD_DBCC1" at 52.682,138.557 h2
  text "PG7" at 48.166,138.377 h1.25
  text "UCPD_FLT" at 26.725,138.325 h2
  text "PI6" at 116.589,138.287 h1.25
  text "PI7" at 105.124,138.218 h1.25
  text "PG6" at 36.2,138.013 h1.25
  text "PG15" at 48.166,137.077 h1.25
  text "PH4" at 105.124,137.018 h1.25
  text "PH5" at 116.589,136.987 h1.25
  text "PG8" at 36.2,136.813 h1.25
  text "UART_CTS" at 94.675,136.375 h1.7
  text "SCL" at 17.77,136.315 h1.2 r90
  text "I2C3" at 16.795,136.24 h1.2 r90
  text "I2C3" at 25.886,136.156 h1.2 r90
  text "SDA" at 26.736,136.156 h1.2 r90
  text "PB4" at 48.166,135.777 h1.25
  text "PH6" at 105.124,135.718 h1.25
  text "PH8" at 116.589,135.687 h1.25
  text "PB3" at 36.2,135.613 h1.25
  text "PB6" at 48.166,134.477 h1.25
  text "PH9" at 105.163,134.413 h1.25
  text "PH10" at 116.589,134.387 h1.25
  text "PB5" at 36.2,134.313 h1.25
  text "PB8" at 48.166,133.277 h1.25
  text "GND" at 105.044,133.206 h1.25
  text "GND" at 36.095,133.115 h1.25
  text "PH11" at 116.589,133.087 h1.25
  text "PB10" at 48.166,131.977 h1.25
  text "PH12" at 105.147,131.911 h1.25
  text "PB9" at 36.2,131.889 h1.25
  text "PH14" at 116.589,131.887 h1.25
  text "RX" at 26.736,131.431 h1.2 r90
  text "TX" at 17.82,131.315 h1.2 r90
  text "UART" at 25.886,130.881 h1.2 r90
  text "PB13" at 48.166,130.777 h1.25
  text "UART" at 16.895,130.715 h1.2 r90
  text "PB12" at 105.147,130.711 h1.25
  text "PB11" at 36.2,130.589 h1.25
  text "PB2" at 116.589,130.587 h1.25
  text "UCPD_DBN" at 26.425,129.85 h2
  text "PC13" at 48.166,129.477 h1.25
  text "PA3" at 105.147,129.411 h1.25
  text "PB14" at 36.2,129.289 h1.25
  text "PA2" at 116.589,129.287 h1.25
  text "GND" at 48.166,128.177 h1.25
  text "PB0" at 116.589,128.087 h1.25
  text "NRST" at 104.76,128.022 h1.25
  text "PB15" at 36.2,127.989 h1.25
  text "PC14" at 48.166,126.877 h1.25
  text "GND" at 116.491,126.822 h1.25
  text "PF6" at 36.2,126.789 h1.25
  text "GND" at 104.915,126.798 h1.25
  text "PC15" at 48.166,125.577 h1.25
  text "PH0" at 105.1,125.516 h1.25
  text "PF7" at 36.2,125.489 h1.25
  text "PB1" at 116.589,125.485 h1.25
  text "PF8" at 36.233,124.334 h1.25
  text "GND" at 48.039,124.282 h1.25
  text "PA6" at 116.589,124.285 h1.25
  text "PH1" at 105.1,124.216 h1.25
  text "PF9" at 36.179,123 h1.25
  text "GND" at 105.1,123 h1.25
  text "PA7" at 116.589,122.985 h1.25
  text "PF10" at 48.243,122.918 h1.25
  text "COMP2_OUT" at 60.675,122 h2 r90
  text "VDDSMPS_CIN" at 86.431,121.985 h2
  text "PF11" at 48.189,121.782 h1.25
  text "PC4" at 36.179,121.756 h1.25
  text "PC1" at 116.604,121.731 h1.25
  text "PC0" at 105.139,121.702 h1.25
  text "TRACE" at 146.8,120.5 h2
  text "PC3" at 116.564,120.484 h1.25
  text "PC5" at 48.26,120.457 h1.25
  text "PC2" at 104.95,120.424 h1.25
  text "GND" at 36.2,120.4 h1.25
  text "GND" at 116.574,119.218 h1.25
  text "PA0" at 48.207,119.186 h1.25
  text "PI0" at 105.218,119.151 h1.25
  text "PH7" at 36.197,119.123 h1.25
  text "PC8" at 105.195,117.967 h1.25
  text "PC9" at 116.608,117.97 h1.25
  text "PA1" at 36.179,117.933 h1.25
  text "PA4" at 48.171,117.887 h1.25
  text "VDDA" at 90.489,117.029 h2
  text "PC10" at 105.171,116.713 h1.25
  text "PA5" at 36.152,116.695 h1.25
  text "PC11" at 116.608,116.654 h1.25
  text "PA8" at 48.207,116.643 h1.25
  text "GND" at 48.207,115.435 h1.25
  text "PC12" at 105.171,115.434 h1.25
  text "VDD" at 36.142,115.408 h1.25
  text "PD2" at 116.515,115.385 h1.25
  text "3V3" at 48.315,114.173 h1.25
  text "5V" at 116.515,114.185 h1.25
  text "GND" at 105.044,114.151 h1.25
  text "5V_DC" at 35.463,114.132 h1.25
  text "I" at 54.495,113.788 h12
  text "K" at 62.3,113.476 h10
  text "IDD" at 38.204,111.943 h2
  text "VDD_MCU" at 47.05,109.6 h2
  text "VDD" at 28.35,109.45 h2
  text "COMP" at 11.573,109.046 h2
  text "POT" at 7.483,108.831 h2
  text "MOD" at 125.796,107.565 h2
  text "VREFP" at 93.789,107.098 h2 r90
  text "OCTO / FLASH_CSn" at 106.678,107.022 h2
  text "OPAMP1 /   VINM" at 82.047,106.901 h2
  text "OPAMP2 /   VINM" at 70.31,106.86 h2
  text "U5" at 114.768,105.456 h2
  text "PB7" at 46.013,104.153 h1.25
  text "PE13" at 95,104.125 h1.25
  text "PE14" at 106.9,104.1 h1.25
  text "PE0" at 58.394,104.078 h1.25
  text "2V8" at 114.225,103.9 h2
  text "TAG" at 139.178,103.47 h2 r90
  text "VDD_ADJ" at 39.422,103.223 h1.5
  text "3V3" at 33.887,103.209 h1.5
  text "PE15" at 106.9,102.9 h1.25
  text "PE1" at 58.394,102.878 h1.25
  text "PE12" at 95,102.8 h1.25
  text "NC" at 46.017,102.742 h1.25
  text "MB1550C" at 75.985,101.743 h4
  text "PD8" at 106.9,101.6 h1.25
  text "NC" at 45.995,101.576 h1.25
  text "PE2" at 58.394,101.578 h1.25
  text "PE11" at 95,101.5 h1.25
  text "PE3" at 58.394,100.378 h1.25
  text "PG12" at 46,100.3 h1.25
  text "PD9" at 106.9,100.3 h1.25
  text "PE10" at 95,100.2 h1.25
  text "J" at 63.066,99.259 h15
  text "GND" at 46,99 h1.25
  text "GND" at 95,99 h1.25
  text "GND" at 106.9,99 h1.25
  text "GND" at 58.394,98.978 h1.25
  text "LDR" at 7.659,98.802 h2
  text "OPAMP" at 12.382,98.706 h2
  text "PG10" at 46,97.8 h1.25
  text "PE9" at 95,97.8 h1.25
  text "PD10" at 106.9,97.8 h1.25
  text "PE4" at 58.394,97.778 h1.25
  text "G" at 37.003,96.815 h10
  text "E" at 28.027,96.64 h12
  text "C" at 19.824,96.52 h10
  text "PE8" at 95,96.5 h1.25
  text "PD11" at 106.9,96.5 h1.25
  text "PG9" at 45.998,96.434 h1.25
  text "PE5" at 58.328,96.4 h1.25
  text "PE6" at 58.328,95.2 h1.25
  text "PE7" at 95,95.2 h1.25
  text "PD12" at 106.9,95.2 h1.25
  text "PD7" at 45.998,95.134 h1.25
  text "PG1" at 95,94 h1.25
  text "PF0" at 58.3,93.9 h1.25
  text "PD13" at 106.9,93.9 h1.25
  text "PD6" at 45.998,93.834 h1.25
  text "PF1" at 58.3,92.7 h1.25
  text "PG0" at 95,92.7 h1.25
  text "PD14" at 106.9,92.7 h1.25
  text "PD5" at 45.998,92.534 h1.25
  text "H" at 37.637,92.022 h10
  text "PF2" at 58.3,91.4 h1.25
  text "PF15" at 95,91.4 h1.25
  text "PD15" at 106.9,91.4 h1.25
  text "PD4" at 45.998,91.334 h1.25
  text "OPAMP1_VOUT" at 4.4,90.7 h2
  text "PF3" at 58.3,90.2 h1.25
  text "PF14" at 95,90.1 h1.25
  text "PG2" at 106.9,90.1 h1.25
  text "PD3" at 45.998,90.034 h1.25
  text "F" at 20.5,89.687 h10
  text "PF4" at 58.3,88.9 h1.25
  text "PF13" at 95,88.9 h1.25
  text "PG3" at 106.9,88.9 h1.25
  text "PD1" at 45.998,88.834 h1.25
  text "MIPI10" at 139.5,88.3 h2 r90
  text "RX" at 16,88.2 h1.5
  text "TX" at 19.4,88.2 h1.5
  text "PF5" at 58.3,87.6 h1.25
  text "PF12" at 95,87.6 h1.25
  text "PG4" at 106.8,87.6 h1.25
  text "PD0" at 45.998,87.534 h1.25
  text "NC" at 58.3,86.4 h1.25
  text "NC" at 95,86.4 h1.25
  text "NC" at 46.233,86.314 h1.25
  text "PG5" at 106.8,86.3 h1.25
  text "FMC_SRAM" at 70.4,85.3 h2 r90
  text "GND" at 58.3,85.1 h1.25
  text "GND" at 95,85.1 h1.25
  text "GND" at 106.8,85.1 h1.25
  text "GND" at 46.1,85 h1.25
  text "3V3" at 58.3,83.9 h1.25
  text "VDD" at 46.1,83.8 h1.25
  text "VDD" at 95,83.8 h1.25
  text "3V3" at 106.8,83.8 h1.25
  text "MFX_SWD" at 3.9,82.7 h2
  text "MFX_UART" at 15.5,82.7 h2
  text "VBAT" at 65.638,76.626 h2
  text "VDD" at 58,75.1 h2
  text "AUX1UC" at 92.5,70.4 h2 r90
  text "AUX2UC" at 94.7,70.4 h2 r90
  text "JTAG" at 143.041,69.972 h2 r90
  text "BBU" at 58.1,69.9 h2
  text "VDD_ADJ" at 22.8,69.4 h2
  text "5V_EN" at 1.2,68 h2
  text "3V3" at 50.383,66.011 h2
  text "5V_CHG" at 11.2,65.7 h2
  text "LCD" at 103.55,63.775 h2
  text "5V_DC" at 11.2,63.1 h2
  text "5V_UCPD" at 11.224,60.777 h2
  text "MB1379A" at 129.425,60.15 h1.25
  text "Camera module" at 129.475,58.95 h1.25
  text "5V_EXT" at 11.224,58.237 h2
  text "STDBY" at 109.121,56.272 h2
  text "5V_SOURCE" at 3.525,56.125 h2 r90
  text "5V_STLK" at 11.224,55.53 h2
  text "TX" at 111.575,51.925 h2
  text "STLK_OVC" at 21.986,48.037 h2 r90
  text "RX" at 111.525,46.075 h2
  text "FDCAN" at 110.875,45.45 h3 r90
  text "FDCAN" at 138.825,42.605 h2 r90
  text "5V" at 4.9,28.1 h2
  text "STLK_NRST" at 11.756,24.134 h2
  text "1V8" at 118.961,23.504 h2
  text "ADF1_CCK0" at 134.405,17.227 h1.7
  text "ADF1_SDIN0" at 114.795,17.138 h1.7
  text "AUDIO_JACK" at 144.898,15.628 h1.7
  text "MDF1_SDIN0" at 134.358,15.389 h1.7
  text "MDF1_CCK0" at 114.952,15.372 h1.7
  text "STLK" at 0.463,15.182 h2
  text "RES" at 11.129,14.54 h2
  text "PASSIVE" at 41.392,11.459 h2
  text "MIC" at 108.589,11.028 h1.5
  text "GND" at 17.284,9.916 h2 r90
  text "1" at 128.79,8.445 h2
  text "MEMS MODULE" at 140.259,4.609 h1.7
  text "0" at 128.689,4.493 h2
  text "TAMPER" at 40.902,2.82 h2 r90
  text "GND" at 116.834,2.696 h2 r90
  text "COM" at 1.6,1.5 h2
  text "JOYSTICK" at 94.34,0.968 h2
  text "RESET" at 29.85,0.884 h2
  text "TAMPER" at 52.15,0.884 h2
  text "USER" at 69.553,0.9 h2
  text "ACTIVE" at 40.713,0.82 h2
  text ".Layer_Name" at 34.834,-69.2 h3
  text ".GTO" at 76.528,-69.2 h3
Bottom Overlay:
  text "I2C SCL" at 39.3,133.275 h1.2
  text "I2C SDA" at 39.025,129.325 h1.2
  text "SDCARD" at 153.993,107.466 h2
  text "OCTOSPI_FLASH" at 137.15,90.175 h2 r270
  text ".GBO" at 65.325,-69.232 h3
  text ".Layer_Name" at 106.639,-69.232 h3
Top Paste:
  text ".Layer_Name" at 34.834,-69.2 h3
  text ".GTP" at 76.528,-69.2 h3
Bottom Paste:
  text ".GBP" at 65.325,-69.232 h3
  text ".Layer_Name" at 106.639,-69.232 h3
Top Solder:
  region: 145.975,4.3 145.975,2.55 153.6,2.55 153.6,4.3
  text ".Layer_Name" at 34.834,-69.2 h3
  text ".GTS" at 76.528,-69.2 h3
Bottom Solder:
  region: 145.975,4.3 145.975,2.55 153.6,2.55 153.6,4.3
  text ".GBS" at 65.325,-69.232 h3
  text ".Layer_Name" at 106.639,-69.232 h3
M1-Board Shape:
  lines w0.1: 154.811,117.648 cw(c157.726,120.648) 154.813,123.65 154.813,169.688 ccw(c153.813,169.688) 153.813,170.688 1,170.688 ccw(c1,169.688) 0,169.688 0,1 ccw(c1,1) 1,0 153.813,0 ccw(c153.813,1) 154.813,1 154.813,117.648
M2-Board Dimensions:
  text ".Layer_Name" at 34.834,-69.2 h3
  text ".GM2" at 76.528,-69.2 h3
M14-Top Assembly:
  text ".Layer_Name" at 34.834,-69.2 h3
  text ".GM14" at 76.528,-69.2 h3
M15-Bottom Assembly:
  text ".GM15" at 65.325,-69.232 h3
  text ".Layer_Name" at 106.639,-69.232 h3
